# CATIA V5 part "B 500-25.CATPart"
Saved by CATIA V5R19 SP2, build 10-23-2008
Part number: B 500-25
Bounding box of the stored display mesh (mm): x -18.951 to 18.951, y -18.952 to 18.952, z 0 to 100
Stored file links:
  C:\Users\Bora\Desktop\3D Katı model\B serisi\B 500\B 500-25.CATPart
  C:\Program Files\Dassault Systemes\B19\intel_a\reffiles\standard\MetricThickPitch.txt
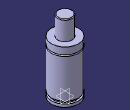
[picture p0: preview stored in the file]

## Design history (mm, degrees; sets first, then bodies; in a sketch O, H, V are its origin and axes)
Body1 (main body)
  Sketch1 on yz-plane, origin (0, 0, 0), H (0, 1, 0), V (0, 0, 1)
    point P3 (10, 99)
    point P5 (10, 99)
    point P7 (19, 63.5)
    point P8 (19, 61.5)
    point P12 (19, 61.5)
    point P13 (19, 63.5)
    line L1 (19, 0) -> (19, 4)
    line L2 (10, 99) -> (10, 73)
    arc A1 centre (9, 99) radius 1 from (10, 99) to (9, 100) ccw
    arc A2 centre (19, 62.5) radius 1 from (19, 63.5) to (19, 61.5) ccw
    line L3 (16.5, 7.5) -> (16.5, 4)
    line L4 (19, 7.5) -> (19, 61.5)
    line L5 (19, 63.5) -> (19, 73)
    line L6 (9, 100) -> (0, 100)
    point P15 (0, 100)
    line L7 (10, 73) -> (19, 73)
    line L8 (0, 0) -> (19, 0)
    line L9 (16.5, 7.5) -> (19, 7.5)
    line L10 (16.5, 4) -> (19, 4)
    tangency: L6 A1
    coincidence: P15 V, P3 P5, P7 P13, P8 P12
    horizontal: L7 H, L8 H, L9 H, L10 H
  Shaft1: profile Sketch1, axis Sketch1.V, angle 360
  Sketch2 on face of Shaft1 from Sketch1.L8, origin (0, 0, 0), H (1, 0, 0), V (0, -1, 0)
    point P1 (0, 0)
  Hole1: placed by Sketch2, at (0, 0, 0) direction (0, 0, 1), diameter 6.647, depth 7, threaded "M8", thread diameter 8, thread depth 7, pitch 1.25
